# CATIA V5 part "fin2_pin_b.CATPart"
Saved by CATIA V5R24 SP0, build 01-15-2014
Part number: Pin B
Bounding box of the stored display mesh (mm): x -1.576 to 1.576, y -1.598 to 1.598, z -12 to 0
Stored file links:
  G:\내 드라이브\04_WORK\00_LECTURE\CAD2020\exam\fin2_pin_b.CATPart
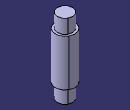
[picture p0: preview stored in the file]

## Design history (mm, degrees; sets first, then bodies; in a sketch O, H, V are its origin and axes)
Body1 (main body)
  Sketch1 on yz-plane, origin (0, 0, 0), H (0, 1, 0), V (0, 0, 1)
    axis line L1 (0, 12.6549) -> (0, -13.7095)
    point P1 (0, 12.6549)
    line L2 (0, 0) -> (-1.25, 0)
    line L3 (-1.25, 0) -> (-1.25, -2.25)
    line L4 (-1.25, -2.25) -> (-1.6, -2.25)
    line L5 (-1.6, -2.25) -> (-1.6, -9.75)
    point P6 (-1.6, -9.75)
    line L6 (-1.6, -9.75) -> (-1.25, -9.75)
    point P7 (-1.25, -9.75)
    line L7 (-1.25, -9.75) -> (-1.25, -12)
    line L8 (-1.25, -12) -> (0, -12)
    point P9 (0, -12)
    line L9 (0, -12) -> (0, 0)
    length L9 = 12
    length L5 = 7.5
    length L3 = 2.25
    distance L3 L1 = 1.25
    distance L5 L1 = 1.6
    distance L8 P6 = 2.25 (reference)
    coincidence: P1 V, P7 L3, P9 L1
    vertical: L1 V, L3 V, L5 V, L7 V, L9 V
    horizontal: L2 H, L6 H, L8 H, L4 H
  Shaft1: profile Sketch1, axis Sketch1.L1, angle 360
